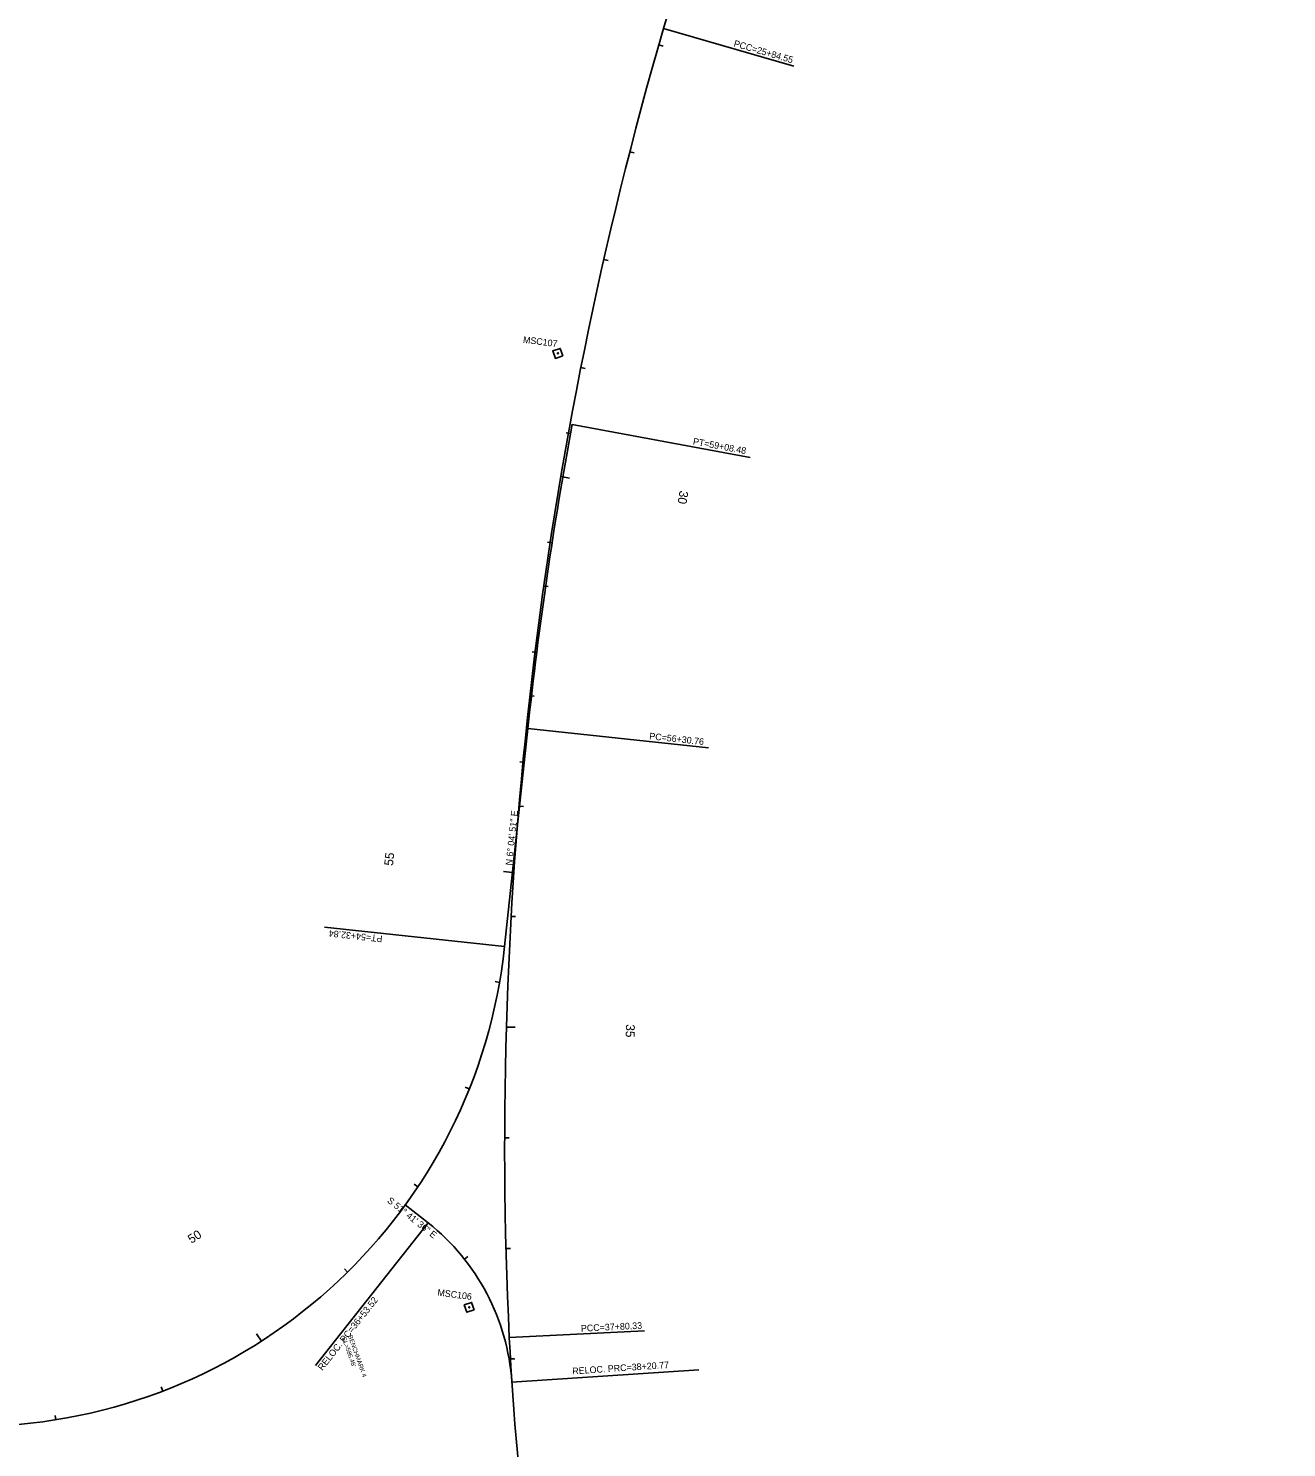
# Model space of a CAD drawing. Extents: x 2004390 to 2008791, y 1133870 to 1140084.
# Drawn here: x 2007099 to 2008236, y 1137269 to 1138550 of the extents above; entities that cross this region are included whole.
import ezdxf

# ---------------------------------------------------------------- set-up
doc = ezdxf.new("R2010")
doc.units = 0
for name, color, linetype in [('RD_HC_Cl', 7, 'Continuous'), ('RD_HC_CL_Rel', 7, 'Continuous'), ('RD_HC_Data', 7, 'Continuous'), ('RD_HC_Data_Rel', 7, 'Continuous'), ('RD_HC_Data_Tic', 7, 'Continuous'), ('RD_HC_Data_Tic_Rel', 7, 'Continuous'), ('RD_HC_Survey', 7, 'Continuous'), ('RD_HC_Survey_txCode', 7, 'Continuous'), ('RD_HC_TX_Rel_Sta50', 7, 'Continuous'), ('RD_HC_TX_Sta50', 7, 'Continuous')]:
    doc.layers.add(name, color=color, linetype=linetype)

msp = doc.modelspace()

# ---------------------------------------------------------------- linework, layer by layer
at = {"layer": 'RD_HC_Cl'}
for centre, radius, start, end in [((2009874, 1137910.4), 2292, 135.6222, 163.7915), ((2011139.8, 1137542.4), 3610.2, 163.7915, 182.769), ((2009823.1, 1137478.8), 2292, 182.769, 203.6507)]:
    msp.add_arc(centre, radius, start, end, dxfattribs=at)
at = {"layer": 'RD_HC_CL_Rel'}
for p, q in [((2007529.5, 1137721.1), (2007550.5, 1137917.9)), ((2007439.9, 1137487.7), (2007460.5, 1137471.4))]:
    msp.add_line(p, q, dxfattribs=at)
for centre, radius, start, end in [((2011127.8, 1137536.8), 3597.5, 169.496, 173.919), ((2007047.3, 1137772.5), 485, 272.4547, 353.919), ((2007336.5, 1137314.5), 200, 3.7798, 51.6934)]:
    msp.add_arc(centre, radius, start, end, dxfattribs=at)
at = {"layer": 'RD_HC_Data'}
for p, q in [((2007673.1, 1138550.2), (2007790.7, 1138516)), ((2007533.8, 1137368), (2007656, 1137373.9))]:
    msp.add_line(p, q, dxfattribs=at)
at = {"layer": 'RD_HC_Data_Rel'}
for p, q in [((2007590.5, 1138192.6), (2007751.3, 1138162.8)), ((2007550.5, 1137917.9), (2007713.8, 1137900.5)), ((2007529.5, 1137721.1), (2007366.9, 1137738.4)), ((2007460.5, 1137471.4), (2007358.7, 1137342.6)), ((2007536.1, 1137327.7), (2007704.9, 1137338.8))]:
    msp.add_line(p, q, dxfattribs=at)
at = {"layer": 'RD_HC_Data_Tic'}
for p, q in [((2007668.8, 1138535.3), (2007672.6, 1138534.2)), ((2007642.6, 1138438.8), (2007646.5, 1138437.8)), ((2007619.1, 1138341.6), (2007623, 1138340.7)), ((2007598.3, 1138243.8), (2007602.3, 1138243)), ((2007580.3, 1138145.5), (2007588.2, 1138144.1)), ((2007564.9, 1138046.6), (2007568.9, 1138046.1)), ((2007552.4, 1137947.4), (2007556.3, 1137947)), ((2007542.5, 1137847.9), (2007546.5, 1137847.6)), ((2007535.4, 1137748.2), (2007539.4, 1137748)), ((2007531.1, 1137648.3), (2007539.1, 1137648.1)), ((2007529.6, 1137548.3), (2007533.6, 1137548.3)), ((2007530.8, 1137448.3), (2007534.8, 1137448.4)), ((2007534.8, 1137348.4), (2007538.8, 1137348.6))]:
    msp.add_line(p, q, dxfattribs=at)
at = {"layer": 'RD_HC_Data_Tic_Rel'}
for p, q in [((2007589, 1138184.3), (2007585.1, 1138185)), ((2007572.4, 1138085.7), (2007568.4, 1138086.3)), ((2007558.5, 1137986.7), (2007554.5, 1137987.2)), ((2007547.2, 1137887.3), (2007543.3, 1137887.7)), ((2007536.6, 1137787.9), (2007528.7, 1137788.7)), ((2007524.9, 1137688.6), (2007521, 1137689.3)), ((2007497.6, 1137592.5), (2007493.9, 1137594)), ((2007451.3, 1137504.1), (2007447.9, 1137506.4)), ((2007493.3, 1137438.7), (2007496.4, 1137441.1)), ((2007387.8, 1137427.1), (2007385, 1137430)), ((2007309.9, 1137364.7), (2007305.5, 1137371.4)), ((2007533.6, 1137348.3), (2007537.6, 1137349)), ((2007220.8, 1137319.6), (2007219.4, 1137323.3)), ((2007124.4, 1137293.6), (2007123.8, 1137297.6))]:
    msp.add_line(p, q, dxfattribs=at)
at = {"layer": 'RD_HC_Survey'}
for points in [[(2007582.2, 1138254.5), (2007579.8, 1138261.2), (2007573.1, 1138258.9), (2007575.5, 1138252.2)], [(2007502.1, 1137393), (2007499.8, 1137399.7), (2007493.1, 1137397.4), (2007495.5, 1137390.7)]]:
    msp.add_lwpolyline(points, close=True, dxfattribs=at)
for centre in [(2007577.7, 1138256.7), (2007497.6, 1137395.2)]:
    msp.add_circle(centre, 0.5, dxfattribs=at)

# ---------------------------------------------------------------- texts
at = {"layer": 'RD_HC_Data'}
for s, rotation, p in [('PCC=25+84.55', 343.7915, (2007736, 1138534)), ('PCC=37+80.33', 2.769, (2007598.6, 1137373.2))]:
    msp.add_text(s, height=6, rotation=rotation, dxfattribs=at).set_placement(p)
at = {"layer": 'RD_HC_Data_Rel'}
for s, rotation, p in [('PT=59+08.48', 349.496, (2007699.3, 1138174.5)), ('PC=56+30.76', 353.919, (2007660, 1137908.2)), ('N 6%%d 04\' 51" E', 83.919, (2007536.3, 1137794)), ('PT=54+32.84', 173.919, (2007419.5, 1137730.8)), ('S 51%%d 41\' 36" E', 321.6934, (2007423, 1137490.5)), ('RELOC. PC=36+53.52', 51.6934, (2007365, 1137337.6)), ('RELOC. PRC=38+20.77', 3.7798, (2007590.9, 1137334.6))]:
    msp.add_text(s, height=6, rotation=rotation, dxfattribs=at).set_placement(p)
at = {"layer": 'RD_HC_Survey_txCode'}
for s, height, rotation, p in [('MSC107', 6, 352.7452, (2007545.9, 1138266.3)), ('MSC106', 6, 352.6957, (2007468.6, 1137405.8)), ("EL=586.46'", 4, 289.4494, (2007382.5, 1137367.3)), ('BENCHMARK 4', 4, 289.4494, (2007388.1, 1137369.3))]:
    msp.add_text(s, height=height, rotation=rotation, dxfattribs=at).set_placement(p)
at = {"layer": 'RD_HC_TX_Rel_Sta50'}
for s, rotation, p in [('55', 83.919, (2007428.7, 1137793.7)), ('50', 32.785, (2007246.7, 1137452.5))]:
    msp.add_text(s, height=8, rotation=rotation, dxfattribs=at).set_placement(p)
at = {"layer": 'RD_HC_TX_Sta50'}
for s, rotation, p in [('30', 260.3848, (2007687.7, 1138133.1)), ('35', 268.3201, (2007639.2, 1137650.9))]:
    msp.add_text(s, height=8, rotation=rotation, dxfattribs=at).set_placement(p)

doc.saveas('drawing.dxf')
